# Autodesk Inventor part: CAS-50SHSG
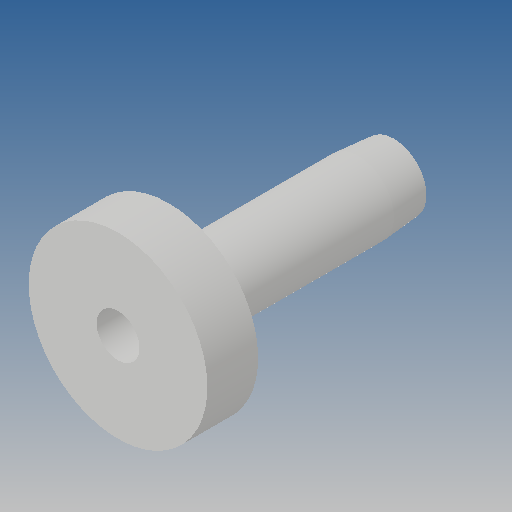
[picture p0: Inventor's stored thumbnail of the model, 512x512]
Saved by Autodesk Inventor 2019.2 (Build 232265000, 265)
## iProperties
Created: 2009-09
Part Number: CAS-50SHSG
Material: Ogólny
Document SubType Name: Modeling
Designer: CADENGINEERING4
Density: 1 g/cm^3
Appearance: Domyślna
Author: CADENGINEERING4
Revision Number: 1LAST_VERSION
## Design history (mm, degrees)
feature "Baza1"
node "Bryła1"
